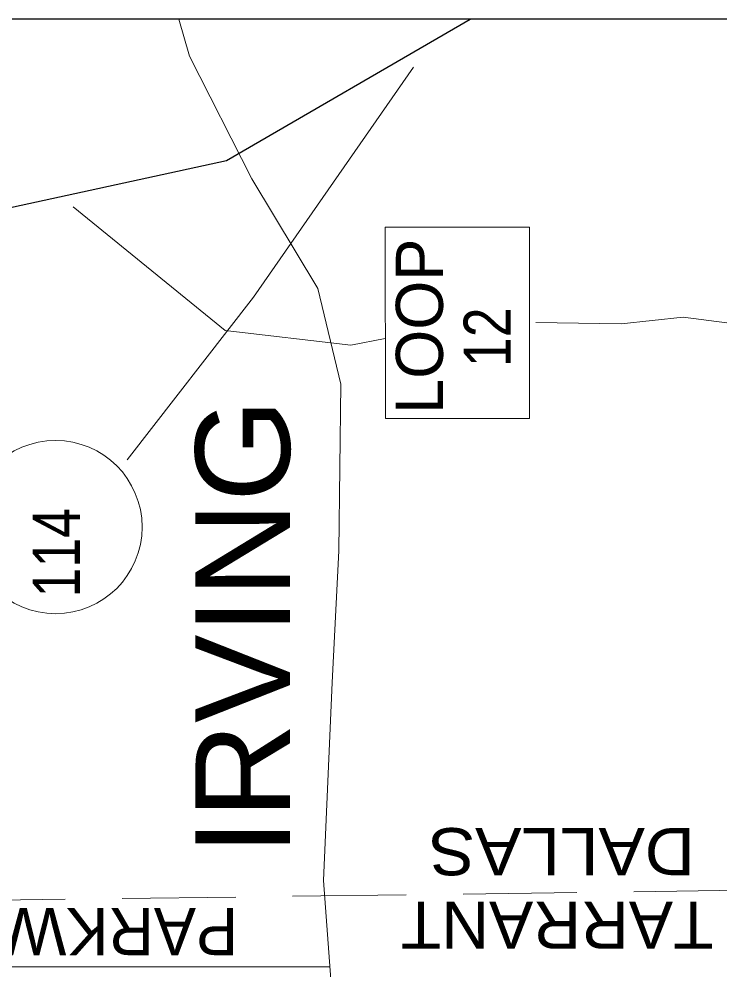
# Model space of a CAD drawing. Extents: x 2363323 to 2367082, y 6956018 to 6980837.
# Drawn here: x 2365911.5 to 2365987.3, y 6980732.7 to 6980835.5 of the extents above; entities that cross this region are included whole.
import ezdxf

# ---------------------------------------------------------------- set-up
doc = ezdxf.new("R2010")
doc.units = 0
doc.header["$LTSCALE"] = 4.1
doc.linetypes.add('MEDIUM_DASHED', pattern=[4.5, 3, -1.5])
doc.layers.add('62', color=7, linetype='Continuous', lineweight=13)
doc.layers.add('63', color=7, linetype='Continuous', lineweight=13)

msp = doc.modelspace()

# ---------------------------------------------------------------- linework, layer by layer
at = {"layer": '62'}
for p, q in [((2365936.848, 6980805.484), (2365954.13, 6980830.326)), ((2365936.848, 6980805.484), (2365923.168, 6980787.909)), ((2365947.358, 6980800.286), (2365951.092, 6980801.006)), ((2365945.086, 6980733.094), (2365876.769, 6980733.094))]:
    msp.add_line(p, q, dxfattribs=at)
at = {"layer": '62', "linetype": 'MEDIUM_DASHED'}
msp.add_line((2365848.822, 6980739.484), (2366129.802, 6980743.218), dxfattribs=at)
at = {"layer": '62', "lineweight": 25}
for points in [[(2365753.976, 6980385.954), (2366219.249, 6980385.954), (2366219.249, 6980835.546), (2365753.974, 6980835.546)], [(2365877.894, 6980803.212), (2365897.762, 6980812.39), (2365933.901, 6980820.244), (2365960.272, 6980835.546)]]:
    msp.add_lwpolyline(points, dxfattribs=at)
at = {"layer": '62'}
for points in [[(2365946.952, 6980705.732), (2365946.12, 6980719.074), (2365944.412, 6980742.408), (2365945.356, 6980763.81), (2365946.075, 6980778.052), (2365946.279, 6980796.078), (2365943.802, 6980806.407), (2365936.646, 6980818.286), (2365929.917, 6980831.541), (2365928.768, 6980835.546)], [(2366035.476, 6980835.546), (2366032.618, 6980826.432), (2366027.778, 6980810.793), (2366014.661, 6980803.953), (2366006.718, 6980802.918), (2365997.558, 6980802.086), (2365990.808, 6980802.356), (2365983.294, 6980803.3), (2365976.588, 6980802.579), (2365967.36, 6980802.74)], [(2365947.358, 6980800.286), (2365933.764, 6980801.884), (2365917.318, 6980815.248)]]:
    msp.add_lwpolyline(points, dxfattribs=at)
msp.add_lwpolyline([(2365951.094, 6980792.342), (2365966.686, 6980792.343), (2365966.686, 6980813.043), (2365951.092, 6980813.043)], close=True, dxfattribs=at)
msp.add_circle((2365915.424, 6980780.62), 9.364, dxfattribs=at)
at = {"layer": '63'}
for p, q in [((2365936.848, 6980805.484), (2365954.13, 6980830.326)), ((2365936.848, 6980805.484), (2365923.168, 6980787.909)), ((2365947.358, 6980800.286), (2365951.092, 6980801.006)), ((2365945.086, 6980733.094), (2365876.769, 6980733.094))]:
    msp.add_line(p, q, dxfattribs=at)
at = {"layer": '63', "linetype": 'MEDIUM_DASHED'}
msp.add_line((2365848.822, 6980739.484), (2366129.802, 6980743.218), dxfattribs=at)
at = {"layer": '63', "lineweight": 25}
for points in [[(2365753.976, 6980385.954), (2366219.249, 6980385.954), (2366219.249, 6980835.546), (2365753.974, 6980835.546)], [(2365877.894, 6980803.212), (2365897.762, 6980812.39), (2365933.901, 6980820.244), (2365960.272, 6980835.546)]]:
    msp.add_lwpolyline(points, dxfattribs=at)
at = {"layer": '63'}
for points in [[(2365946.952, 6980705.732), (2365946.12, 6980719.074), (2365944.412, 6980742.408), (2365945.356, 6980763.81), (2365946.075, 6980778.052), (2365946.279, 6980796.078), (2365943.802, 6980806.407), (2365936.646, 6980818.286), (2365929.917, 6980831.541), (2365928.768, 6980835.546)], [(2366035.476, 6980835.546), (2366032.618, 6980826.432), (2366027.778, 6980810.793), (2366014.661, 6980803.953), (2366006.718, 6980802.918), (2365997.558, 6980802.086), (2365990.808, 6980802.356), (2365983.294, 6980803.3), (2365976.588, 6980802.579), (2365967.36, 6980802.74)], [(2365947.358, 6980800.286), (2365933.764, 6980801.884), (2365917.318, 6980815.248)]]:
    msp.add_lwpolyline(points, dxfattribs=at)
msp.add_lwpolyline([(2365951.094, 6980792.342), (2365966.686, 6980792.343), (2365966.686, 6980813.043), (2365951.092, 6980813.043)], close=True, dxfattribs=at)
msp.add_circle((2365915.424, 6980780.62), 9.364, dxfattribs=at)

# ---------------------------------------------------------------- texts
at = {"layer": '62'}
for s, rotation, p in [('LOOP', 90, (2365957.325, 6980792.859)), ('PARKWAY', 180, (2365935.159, 6980739.44))]:
    msp.add_text(s, height=5.099, rotation=rotation, dxfattribs=at).set_placement(p)
for s, height, rotation, width, p in [('12', 5.099, 90, 0.85, (2365964.661, 6980797.922)), ('IRVING', 10.21, 90, 1.05, (2365940.765, 6980745.11)), ('114', 5.099, 90, 0.85, (2365918.059, 6980773.014)), ('DALLAS', 5.099, 180, 1.1, (2365984.575, 6980748.081)), ('TARRANT', 5.099, 180, 1.05, (2365986.577, 6980740.137))]:
    msp.add_text(s, height=height, rotation=rotation, dxfattribs=dict(at, width=width)).set_placement(p)
at = {"layer": '63'}
for s, rotation, p in [('LOOP', 90, (2365957.325, 6980792.859)), ('PARKWAY', 180, (2365935.159, 6980739.44))]:
    msp.add_text(s, height=5.099, rotation=rotation, dxfattribs=at).set_placement(p)
for s, height, rotation, width, p in [('12', 5.099, 90, 0.85, (2365964.661, 6980797.922)), ('IRVING', 10.21, 90, 1.05, (2365940.765, 6980745.11)), ('114', 5.099, 90, 0.85, (2365918.059, 6980773.014)), ('DALLAS', 5.099, 180, 1.1, (2365984.575, 6980748.081)), ('TARRANT', 5.099, 180, 1.05, (2365986.577, 6980740.137))]:
    msp.add_text(s, height=height, rotation=rotation, dxfattribs=dict(at, width=width)).set_placement(p)

doc.saveas('drawing.dxf')
